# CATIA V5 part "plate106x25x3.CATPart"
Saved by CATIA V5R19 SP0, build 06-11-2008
Part number: plate106x25x3
Bounding box of the stored display mesh (mm): x -106 to 0, y 0 to 3, z 0 to 25
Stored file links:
  D:\AUTO BATCH (BHEL)\Hexagonal Dome\plate106x25x3.CATPart
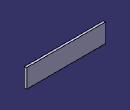
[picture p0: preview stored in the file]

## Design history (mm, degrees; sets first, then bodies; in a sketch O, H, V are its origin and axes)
SheetMetalParameters1: BendRadius 3, ReliefAxialLength 2, ReliefRadialLength 1, MinimumBendRadius 0, Thickness 3, KFactor 0.325257 {= log(min(100,max(20*SheetMetalParameters1.BendRadius,SheetMetalParameters1.Thickness)/SheetMetalParameters1.Thickness))/log(100)/2}
Body1 (main body)
  Sketch1 on zx-plane, origin (0, 0, 0), H (-1, 0, 0), V (0, 0, 1)
    line L1 (0, 0) -> (106, 0)
    line L2 (106, 0) -> (106, 25)
    line L3 (106, 25) -> (0, 25)
    line L4 (0, 25) -> (0, 0)
    length L1 = 106
    length L2 = 25
    horizontal: L1 H, L3 H
    vertical: L2 V, L4 V
  Wall1: Thickness 3, Profile Sketch1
